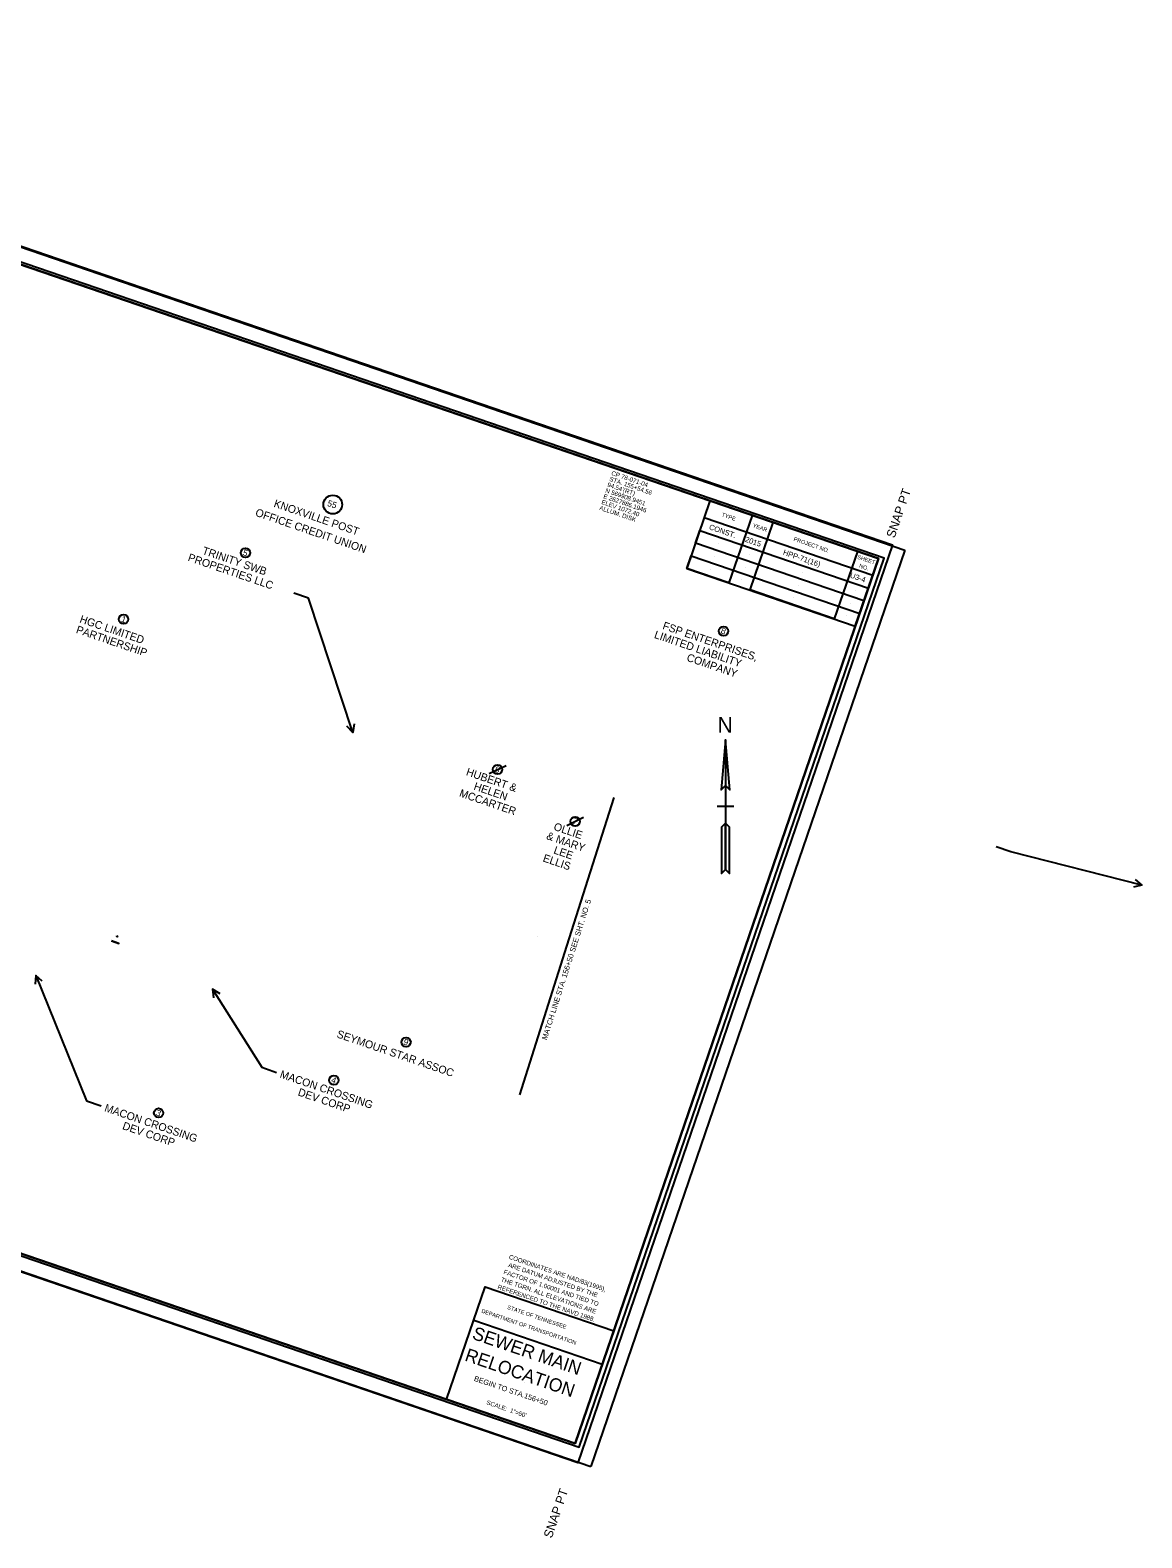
# Model space of a CAD drawing. Extents: x 2626331 to 2628652, y 569305 to 571035.
# Drawn here: x 2627404 to 2628652, y 569305 to 570998 of the extents above; entities that cross this region are included whole.
import ezdxf

# ---------------------------------------------------------------- set-up
doc = ezdxf.new("R2010")
doc.units = 0
for name, color, linetype in [('DESIGN - CENTERLINE - Proposed Text', 7, 'Continuous'), ('DESIGN - SCRATCH - User 1', 7, 'Continuous'), ('DESIGN - SHEET - Corner Text', 7, 'Continuous'), ('DESIGN - SHEET - Light Grid', 7, 'Continuous'), ('DESIGN - SHEET - Linework', 7, 'Continuous'), ('DESIGN - SHEET - Plot Shape', 7, 'Continuous'), ('SURVEY - CONTROL with Text', 7, 'Continuous'), ('SURVEY - PROPERTY - Owners', 7, 'Continuous'), ('SURVEY - PROPERTY - Tract Numbers', 7, 'Continuous')]:
    doc.layers.add(name, color=color, linetype=linetype)

msp = doc.modelspace()

# ---------------------------------------------------------------- linework, layer by layer
at = {"layer": 'DESIGN - CENTERLINE - Proposed Text'}
for p, q in [((2628184.4, 570126.4), (2628175, 570126.4)), ((2628193.9, 570126.4), (2628184.4, 570126.4))]:
    msp.add_line(p, q, dxfattribs=at)
for points in [[(2628184.4, 570201.4), (2628179.5, 570145.1), (2628184.4, 570150), (2628189.3, 570145.1), (2628184.4, 570201.4), (2628184.4, 570055.9), (2628189, 570051.4), (2628189, 570103.1), (2628184.4, 570107.7), (2628179.9, 570103.1), (2628179.9, 570051.4), (2628184.4, 570055.9)], [(2627953.5, 569802.8), (2628006.4, 569969.6), (2628059.3, 570136.4)]]:
    msp.add_lwpolyline(points, dxfattribs=at)
for points in [[(2628184.4, 570150), (2628189.3, 570145.1), (2628184.4, 570201.4)], [(2628179.9, 570051.4), (2628184.4, 570055.9), (2628184.4, 570107.7), (2628179.9, 570103.1)]]:
    msp.add_lwpolyline(points, close=True, dxfattribs=at)
at = {"layer": 'DESIGN - SCRATCH - User 1'}
for p, q in [((2628181.7, 570435.4), (2628181.7, 570435.4)), ((2628176.8, 570421.2), (2628176.8, 570421.2)), ((2628216.7, 570423.4), (2628216.7, 570423.4)), ((2628172, 570407), (2628172, 570407)), ((2628207, 570395), (2628207, 570395)), ((2628211.8, 570409.2), (2628211.8, 570409.2)), ((2628275.8, 570403.1), (2628275.8, 570403.1)), ((2628167.1, 570392.8), (2628167.1, 570392.8)), ((2628202.1, 570380.8), (2628202.1, 570380.8)), ((2628270.9, 570388.9), (2628270.9, 570388.9)), ((2628334.9, 570382.9), (2628334.9, 570382.9)), ((2628266.1, 570374.8), (2628266.1, 570374.8)), ((2628330.1, 570368.7), (2628330.1, 570368.7)), ((2628261.2, 570360.6), (2628261.2, 570360.6)), ((2628325.2, 570354.5), (2628325.2, 570354.5)), ((2628320.3, 570340.3), (2628320.3, 570340.3)), ((2627973.8, 569980.7), (2627973.8, 569980.7)), ((2627958.7, 569480.4), (2627958.7, 569480.4))]:
    msp.add_line(p, q, dxfattribs=at)
at = {"layer": 'DESIGN - SHEET - Light Grid'}
msp.add_lwpolyline([(2626445.3, 569947.1), (2628020.3, 569407.2), (2628362.4, 570405.2), (2626787.4, 570945.1)], close=True, dxfattribs=at)
at = {"layer": 'DESIGN - SHEET - Linework'}
for p, q in [((2626683.1, 570997.9), (2628385.9, 570414.3)), ((2628385.9, 570414.3), (2628033.2, 569385.6)), ((2626330.5, 569969.3), (2628033.2, 569385.6))]:
    msp.add_line(p, q, dxfattribs=at)
for points in [[(2626867, 570915.1), (2626526.5, 569921.9), (2628015.7, 569411.4), (2628356.1, 570404.7), (2626867, 570915.1)], [(2628166.9, 570469.5), (2628141, 570393.8), (2628330.2, 570329), (2628356.1, 570404.7), (2628332.5, 570412.8), (2628306.5, 570337.1), (2628212, 570369.5), (2628237.9, 570445.2), (2628214.2, 570453.3), (2628188.3, 570377.6), (2628141, 570393.8), (2628145.9, 570408), (2628335.1, 570343.2), (2628339.9, 570357.4), (2628150.7, 570422.2), (2628155.6, 570436.4), (2628344.8, 570371.6), (2628349.7, 570385.7), (2628160.5, 570450.6)], [(2627871.4, 569460.9), (2627914.7, 569587.3), (2628059, 569537.8), (2628046, 569500), (2627901.8, 569549.4)]]:
    msp.add_lwpolyline(points, dxfattribs=at)
at = {"layer": 'DESIGN - SHEET - Plot Shape'}
for points in [[(2626763.7, 570971.4), (2628371.8, 570420.1), (2628018.6, 569389.6), (2626410.4, 569940.8)], [(2626786.5, 570942.7), (2628356.1, 570404.7), (2628015.7, 569411.4), (2626446.1, 569949.5)]]:
    msp.add_lwpolyline(points, close=True, dxfattribs=at)
at = {"layer": 'SURVEY - CONTROL with Text'}
for points in [[(2627495.3, 569975.5), (2627503.3, 569972.7), (2627503.3, 569972.7), (2627495.3, 569975.5)], [(2627501.2, 569981.2), (2627501.9, 569980.9), (2627501.7, 569980.3), (2627501, 569980.5)]]:
    msp.add_lwpolyline(points, close=True, dxfattribs=at)
at = {"layer": 'SURVEY - PROPERTY - Tract Numbers'}
for p, q in [((2627919.2, 570163.4), (2627938.1, 570172.6)), ((2628006.3, 570105.1), (2628025.1, 570114.4))]:
    msp.add_line(p, q, dxfattribs=at)
for points in [[(2627716.4, 570360.5), (2627699.9, 570366.1)], [(2627766.1, 570209.6), (2627716.4, 570360.5)], [(2627767.5, 570219.3), (2627766.1, 570209.6), (2627759.2, 570216.5)], [(2628504.8, 570075.4), (2628488.2, 570081.1)], [(2628651.8, 570038), (2628504.8, 570075.4)], [(2628644.4, 570044.4), (2628651.8, 570038), (2628642.3, 570035.9)], [(2627417.4, 569930.4), (2627410.1, 569936.9), (2627409.3, 569927.1)], [(2627410.1, 569936.9), (2627467, 569796)], [(2627608.6, 569921.3), (2627664, 569833.7)], [(2627617, 569916.3), (2627608.6, 569921.3), (2627609.6, 569911.6)], [(2627664, 569833.7), (2627680.5, 569828)], [(2627467, 569796), (2627483.6, 569790.3)]]:
    msp.add_lwpolyline(points, dxfattribs=at)
for centre, radius in [((2627743.6, 570465.4), 10.5), ((2627645.5, 570411.2), 5.25), ((2627508.7, 570336.6), 5.25), ((2628182.3, 570323.4), 5.25), ((2627928.6, 570168), 5.25), ((2628015.7, 570109.7), 5.25), ((2627825.8, 569861.9), 5.25), ((2627744.8, 569819.2), 5.25), ((2627548.1, 569782.4), 5.25)]:
    msp.add_circle(centre, radius, dxfattribs=at)

# ---------------------------------------------------------------- texts
at = {"layer": 'DESIGN - CENTERLINE - Proposed Text'}
msp.add_text('N', height=17.7, dxfattribs=at).set_placement((2628175.4, 570209.4))
msp.add_text('MATCH LINE STA. 156+50 SEE SHT. NO. 5', height=6, rotation=72.3958, dxfattribs=at).set_placement((2627983.8, 569863.8))
at = {"layer": 'DESIGN - SHEET - Corner Text'}
for s, height, rotation, p in [('  SNAP PT', 10, 71.0785, (2628371.8, 570420.1)), ('TYPE', 4.5, 341.0785, (2628179.7, 570452.2)), ('CONST.', 6, 341.0785, (2628165.4, 570437.8)), ('2015', 6, 341.0785, (2628205.9, 570423.9)), ('YEAR', 4.5, 341.0785, (2628214.5, 570440.1)), ('PROJECT NO.', 4.5, 341.0785, (2628260.5, 570424.8)), ('HPP-71(16)', 6, 341.0785, (2628248.5, 570409.3)), ('SHEET', 4.5, 341.0785, (2628332, 570404.7)), ('NO.', 4.5, 341.0785, (2628334, 570394.8)), ('U3-4', 6, 341.0785, (2628323.6, 570383.6)), ('COORDINATES ARE NAD/83(1995),', 5, 341.0785, (2627940.8, 569618.9)), ('FACTOR OF 1.00001 AND TIED TO', 5, 341.0785, (2627934.8, 569601.9)), ('ARE DATUM ADJUSTED BY THE', 5, 341.0785, (2627940, 569609.7)), ('REFERENCED TO THE NAVD 1988.', 5, 341.0785, (2627928.1, 569585.2)), ('THE TGRN. ALL ELEVATIONS ARE', 5, 341.0785, (2627931.8, 569593.4)), ('STATE OF TENNESSEE', 4.5, 341.0785, (2627939, 569562.5)), ('DEPARTMENT OF TRANSPORTATION', 4.5, 341.0785, (2627910, 569558.4)), ('SEWER MAIN', 14.76, 341.0785, (2627899.1, 569529.1)), ('RELOCATION', 14.76, 341.0785, (2627890.8, 569504.7)), ('BEGIN TO STA.156+50', 5.905, 341.0785, (2627901.6, 569481.9)), ('SCALE:  1"=50\'', 4.921, 341.0785, (2627915.6, 569455.5)), ('SNAP PT  ', 10, 71.0785, (2627989.4, 569304.4))]:
    msp.add_text(s, height=height, rotation=rotation, dxfattribs=at).set_placement(p)
at = {"layer": 'SURVEY - CONTROL with Text'}
for s, p in [('CP 78-071-04', (2628055.8, 570498.7)), ('N 569908.9451', (2628049.1, 570479.2)), ("94.54'(RT)", (2628051.3, 570485.7)), ('STA. 155+54.56', (2628053.6, 570492.2)), ('ALLUM. DISK', (2628042.4, 570459.7)), ('ELEV 1072.40', (2628044.7, 570466.2)), ('E 2627886.1946', (2628046.9, 570472.7))]:
    msp.add_text(s, height=5, rotation=341.0785, dxfattribs=at).set_placement(p)
at = {"layer": 'SURVEY - PROPERTY - Owners'}
for s, p in [('KNOXVILLE POST ', (2627676.6, 570463.1)), ('OFFICE CREDIT UNION', (2627655.9, 570453)), ('TRINITY SWB', (2627596.3, 570410.2)), ('PROPERTIES LLC', (2627580.2, 570402.5)), ('PARTNERSHIP', (2627454.7, 570321.5)), ('HGC LIMITED', (2627458.7, 570333.3)), ('FSP ENTERPRISES,', (2628113.1, 570325.9)), ('LIMITED LIABILITY', (2628103.7, 570315.9)), ('COMPANY', (2628140.1, 570290.2)), ('HUBERT &', (2627892.5, 570161.8)), ('MCCARTER', (2627884.9, 570138)), ('HELEN', (2627901.1, 570145.6)), ('OLLIE', (2627990.8, 570100.4)), ('& MARY', (2627982.7, 570090)), ('LEE', (2627990.8, 570074)), ('ELLIS', (2627978.7, 570065)), ('SEYMOUR STAR ASSOC', (2627747.3, 569867.5)), ('MACON CROSSING', (2627683.5, 569822.4)), ('DEV CORP', (2627703.7, 569802.3)), ('MACON CROSSING', (2627486.5, 569784.6)), ('DEV CORP', (2627506.7, 569764.5))]:
    msp.add_text(s, height=8.75, rotation=341.0785, dxfattribs=at).set_placement(p)
at = {"layer": 'SURVEY - PROPERTY - Tract Numbers'}
for s, p in [('55', (2627736.8, 570464.1)), ('5', (2627641.9, 570408.7)), ('1', (2627505.4, 570334.1)), ('8', (2628178.6, 570321)), ('6', (2627924.9, 570165.6)), ('7', (2628012.1, 570107.3)), ('9', (2627822.2, 569859.5)), ('4', (2627741.2, 569816.8)), ('3', (2627544.5, 569779.9))]:
    msp.add_text(s, height=7, rotation=341.0785, dxfattribs=at).set_placement(p)

doc.saveas('drawing.dxf')
